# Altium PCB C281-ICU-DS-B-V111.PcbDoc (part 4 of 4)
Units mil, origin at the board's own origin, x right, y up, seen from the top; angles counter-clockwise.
Board outline 9370.03 x 5995.03 mil, 2 copper layers (Top Layer, Bottom Layer); 468 components, 321 nets, 1241 pads, 808 vias.
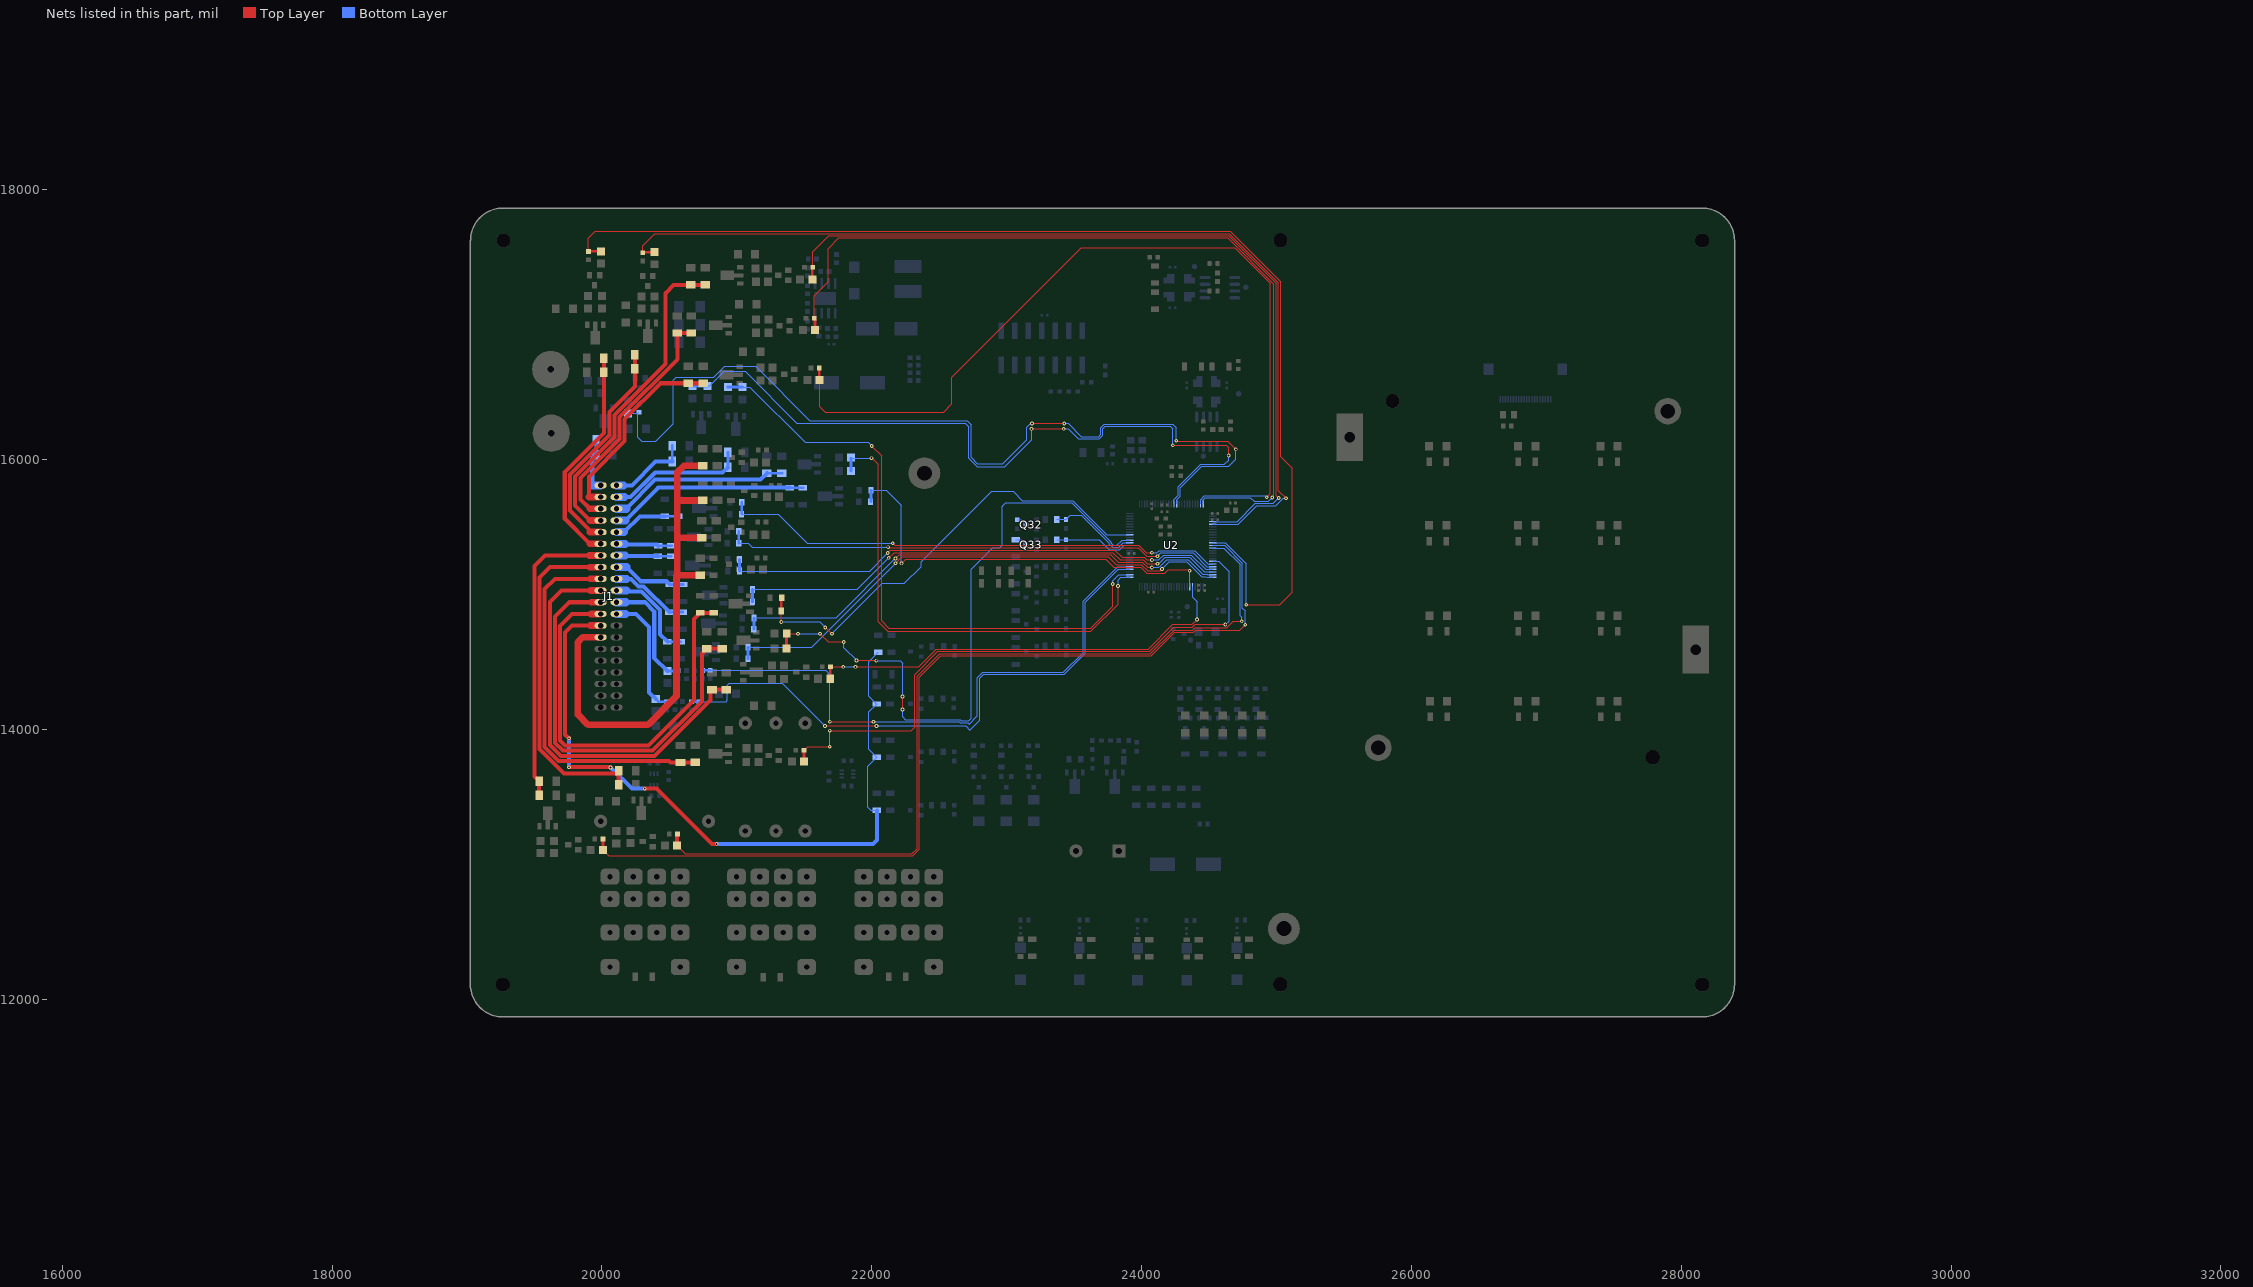
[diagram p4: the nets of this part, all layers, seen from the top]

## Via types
v1: diameter 27.56, hole 13.78, Top Layer to Bottom Layer, tented both sides, 808 vias

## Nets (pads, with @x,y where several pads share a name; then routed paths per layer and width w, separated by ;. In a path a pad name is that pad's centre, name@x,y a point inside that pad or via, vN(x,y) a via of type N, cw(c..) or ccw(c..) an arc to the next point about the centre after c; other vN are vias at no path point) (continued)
按键5: Q33.C R193.2 | length 90.8
  Bottom Layer w7.87: R193.2@23066,15407 23103.86,15407 Q33.C@23141.26,15369.6
按键5_MCU: R189.1 R194.2 U2.13 | length 584.4
  Bottom Layer w7.87: R189.1@23371.61,15407 R194.2@23440,15407 23686.52,15407 23759.52,15334 23839,15334 23870,15365 U2.13@23912.91,15365
按键6: Q32.C R195.2 | length 78.9
  Bottom Layer w7.87: R195.2@23078,15555 23107.11,15555 Q32.C@23142.32,15519.78
按键6_MCU: R188.1 R190.2 U2.14 | length 670
  Bottom Layer w7.87: R188.1@23372,15557.19 23439.19,15557.19 R190.2@23440,15558 23470.45,15588.45 23552.74,15588.45 23760.66,15380.53 23760.66,15374.88 23785.14,15350.39 23829.39,15350.39 23863.69,15384.68 U2.14@23912.91,15384.68
正控_1: J1.11 R53.2 R57.2 | length 3027.7
  Top Layer w30: 19914.47,15030.53 19699.53,15030.53 19613.62,14944.62 19613.62,13886.5 19694.69,13805.43 20389.43,13805.43 20804,14220 20804,14283.97 R57.2@20815.79,14295.77 ; R57.2@20837.77,14295.77 R53.2@20919.22,14295.77
  Top Layer w50: 19914.47,15030.53 J1.11@19989.89,15030.53
正控_1_MCU: R161.2 R199.2 U2.80 | length 3205.8
  Top Layer w7.87: R199.2@21692.05,14463 R199.2@21694.05,14463 ; R199.2@21694.05,14465 v1(21788,14465) ; v1(21880,14465) 22348.58,14465 22478.09,14594.5 24047.5,14594.5 24231.97,14778.97 24374.03,14778.97 v1(24410.53,14815.47)
  Top Layer w20: R161.2@21692.05,14377 R199.2@21692.05,14463
  Bottom Layer w7.87: v1(21788,14465) v1(21880,14465) ; U2.80@24377.48,15057.91 24377.48,14981.52 24410.53,14948.47 v1(24410.53,14815.47)
正控_2: J1.12 R60.2 R61.2 | length 2777.7
  Top Layer w30: 19913.87,15117.14 19652.14,15117.14 19575.75,15040.75 19575.75,13870.81 19679,13767.56 20495.44,13767.56 20506.8,13756.2 R61.2@20582,13756.2 20689.5,13756.2 R60.2@20690,13756.7
  Top Layer w50: 19913.87,15117.14 J1.12@19989.89,15117.14
正控_2_MCU: R165.2 R200.2 U2.69 | length 4450.1
  Top Layer w7.87: R200.2@21497.69,13847 21523.87,13873.19 v1(21688.19,13873.19) ; v1(21688.19,13992.29) 22294.29,13992.29 22320.24,14018.24 22320.24,14408.24 22490.76,14578.76 24058.76,14578.76 24238.49,14758.49 24375.82,14758.49 24396.33,14779 v1(24620.64,14779)
  Top Layer w20: R165.2@21497.69,13762 R200.2@21497.69,13847
  Bottom Layer w7.87: v1(21688.19,13873.19) v1(21688.19,13992.29) ; U2.69@24527.09,15246.89 24571.03,15246.89 24649,15168.92 24649,14804 24624,14779 v1(24620.64,14779)
正控_3: J1.13 R63.2 R64.2 | length 2526.2
  Top Layer w30: 19911.76,15203.76 19615.76,15203.76 19537.87,15125.87 19537.87,13855.13 19717,13676 20106.08,13676 R64.2@20124.01,13693.93 R63.2@20124.01,13590.5
  Top Layer w50: 19911.76,15203.76 J1.13@19989.89,15203.76
正控_3_MCU: R168.2 R201.2 U2.64 | length 6440.2
  Top Layer w7.87: R168.2@20556,13141 20618.25,13078.75 22297,13078.75 22335.99,13117.74 22335.99,14395.99 22503.01,14563.01 24065.28,14563.01 24240.38,14738.11 24377.71,14738.11 24393.01,14753.41 24631.24,14753.41 24679.83,14802 v1(24742,14802)
  Top Layer w30: R168.2@20556,13141 20556,13222 R201.2@20559,13225
  Bottom Layer w7.87: U2.64@24527.09,15345.32 24609.46,15345.32 24730,15224.78 24730,14843 24742,14831 v1(24742,14802)
正控_4: J1.14 R68.2 R69.2 | length 2233.6
  Top Layer w30: R68.2@19534.04,13514.29 R69.2@19534.04,13617.72 19500,13651.75 19500,15211 19579.37,15290.37 19906.37,15290.37
  Top Layer w50: 19906.37,15290.37 J1.14@19989.89,15290.37
正控_4_MCU: R170.2 R202.2 U2.63 | length 7060.2
  Top Layer w7.87: R170.2@20006,13108 20051,13063 22303.52,13063 22351.74,13111.21 22351.74,14389.47 22509.53,14547.26 24071.8,14547.26 24245.67,14721.13 24383,14721.13 24399.53,14737.66 24728.66,14737.66 v1(24768,14777)
  Top Layer w20: R170.2@20006,13108 20007.31,13109.31 R202.2@20007.31,13189
  Bottom Layer w7.87: U2.63@24527.09,15365 24615,15365 24747,15233 24747,14900 24768,14879 v1(24768,14777)
正控_5: J1.15 R81.2 R84.2 | length 1729.1
  Top Layer w30: 19910.02,15376.98 19724.25,15562.75 19724.25,15909.25 20014.96,16199.96 R81.2@20014.96,16725.39 ; R84.2@20013.95,16649.62 R81.2@20013.95,16753.05
  Top Layer w50: 19910.02,15376.98 J1.15@19989.89,15376.98
正控_5_MCU: R171.2 R203.2 U2.62 | length 8830.6
  Top Layer w7.87: R203.2@19900,17543.31 19900,17642.81 19949.19,17692 24657.42,17692 25029.5,17319.93 25029.5,16022.71 25116,15936.21 25116,15016.69 25025,14925.69 v1(24775.37,14925.69)
  Top Layer w20: R203.2@19900,17543.31 19901.47,17544.78 R171.2@19992,17544.78
  Bottom Layer w7.87: U2.62@24527.09,15384.69 24621.41,15384.69 24775.37,15230.73 v1(24775.37,14925.69)
正控_6: J1.16 R131.2 R132.2 | length 1654.3
  Top Layer w30: 19909.4,15463.6 19909.4,15477.82 19762.13,15625.1 19762.13,15892.25 20055,16185.12 20055,16354.87 20243.24,16543.12 R132.2@20243.24,16673.69 R131.2@20243.24,16777.12
  Top Layer w50: 19909.4,15463.6 J1.16@19989.89,15463.6
正控_6_MCU: R196.2 R204.2 U2.55 | length 7287
  Top Layer w7.87: R204.2@20302,17534 20302,17586.78 20391.47,17676.25 24650.9,17676.25 25013.75,17313.4 25013.75,15771.83 v1(25071,15714.58)
  Top Layer w20: R204.2@20302,17534 20307,17539 R196.2@20389,17539
  Bottom Layer w7.87: U2.55@24527.09,15522.48 24716.48,15522.48 24854.21,15660.21 24995.4,15660.21 25049.77,15714.58 v1(25071,15714.58)
正控_7: J1.17 R41.2 R42.2 | length 2407.7
  Top Layer w30: 19911.79,15550.21 19800,15662 19800,15876.56 20092.87,16169.44 20092.87,16331.68 20470,16708.81 20470,17234 20531.74,17295.74 20762.45,17295.74 R41.2@20765.23,17298.52
  Top Layer w50: 19911.79,15550.21 J1.17@19989.89,15550.21
正控_7_MCU: R158.2 R197.2 U2.54 | length 5997.1
  Top Layer w7.87: R197.2@21562,17427 21562,17541.3 21681.2,17660.5 24644.38,17660.5 24998,17306.88 24998,15735 v1(25016,15717)
  Top Layer w20: R158.2@21559,17336 21559,17424 R197.2@21562,17427
  Bottom Layer w7.87: U2.54@24527.09,15542.17 24708.61,15542.17 24842.4,15675.96 24974.96,15675.96 v1(25016,15717)
正控_8: J1.18 R222.2 R223.2 | length 1812.2
  Top Layer w30: 19909.83,15636.83 19841,15705.66 19841,15864 20130.75,16153.75 20130.75,16316 20559.57,16744.82 R223.2@20559.57,16939.36 R222.2@20663,16939.36
  Top Layer w50: 19909.83,15636.83 J1.18@19989.89,15636.83
正控_8_MCU: R226.2 R231.2 U2.50 | length 6285.9
  Top Layer w7.87: R231.2@21573,17049 21573,17215 21677,17319 21677,17565.63 21756.13,17644.76 24637.85,17644.76 24980,17302.61 24980,15732 v1(24968,15720)
  Top Layer w20: R231.2@21573,17049 21579,17043 R226.2@21579,16962.35
  Bottom Layer w7.87: U2.50@24456.22,15672.09 24456.22,15702.68 24472.36,15718.82 24806.18,15718.82 24833.29,15691.71 24939.71,15691.71 v1(24968,15720)
正控_9: J1.19 R218.2 R219.2 | length 1572.1
  Top Layer w30: 19904.56,15723.44 19904.56,15874 20168.62,16138.06 20168.62,16300.31 20435.32,16567.01 R218.2@20749.5,16567.01 20749,16566.51 R219.2@20640.5,16566.51
  Top Layer w50: 19904.56,15723.44 J1.19@19989.89,15723.44
正控_9_MCU: R224.2 R227.2 U2.49 | length 6512.1
  Top Layer w7.87: R224.2@21613,16580 21613,16394.73 21656.05,16351.68 22531.64,16351.68 22594,16414.04 22594,16613 23551,17570 24690.34,17570 24952.51,17307.83 24952.51,15746.74 v1(24927.77,15722)
  Top Layer w20: R227.2@21611,16681 21611,16582 R224.2@21613,16580
  Bottom Layer w7.87: U2.49@24436.54,15672.09 24436.54,15705.26 24465.84,15734.57 24915.2,15734.57 v1(24927.77,15722)
正控_10: J1.20 R220.2 R221.2 | length 411.8
  Bottom Layer w16: R221.2@19954.02,16037.35 R221.2@19956.01,16039.34
  Bottom Layer w20: R221.2@19956.01,16039.34 R220.2@19956.01,16148.35
  Bottom Layer w30: 19927.97,15810.06 19927.97,16011.3 R221.2@19954.02,16037.35
  Bottom Layer w60: 19927.97,15810.06 J1.20@19989.89,15810.06
正控_10_MCU: R225.2 R228.2 U2.40 | length 6688.9
  Top Layer w7.87: v1(23187.63,16269) v1(23427,16269) ; v1(24257.14,16141) 24262.33,16135.82 24639.82,16135.82 v1(24698.64,16077)
  Bottom Layer w7.87: R225.2@20194,16343.85 R228.2@20266.12,16343.85 ; R228.2@20274,16351.73 R228.2@20266.12,16343.85 ; v1(23187.63,16269) 23178,16269 23149,16240 23149,16148 22972,15971 22782,15971 22736,16017 22736,16260 22706,16290 21542,16290 21140.07,16691.93 20908.93,16691.93 20829,16612 20550.71,16612 20529.63,16590.92 20529.63,16267.63 20400.32,16138.32 20294.31,16138.32 20264.23,16168.4 20264.23,16341.96 R228.2@20266.12,16343.85 ; v1(23427,16269) 23457,16269 23554.37,16171.63 23681.31,16171.63 23697,16187.33 23697,16235.61 23724.39,16263 24232,16263 24257.14,16237.86 v1(24257.14,16141) ; U2.40@24259.37,15672.09 24259.37,15702.37 24286.93,15729.93 24286.93,15793.47 24444.46,15951 24646.7,15951 24698.64,16002.94 v1(24698.64,16077)
水温: J1.7 R245.1 R247.1 R257.1 R263.1 | length 3986.8
  Top Layer w50: J1.7@19989.89,14684.07 19857.07,14684.07 19821,14648 19821,14112 19898,14035 20340,14035 20553,14248 20553,15140 20557.62,15144.62 ; R257.1@20729.26,15144.62 20557.62,15144.62 ; R263.1@20739.79,15421.52 20561.13,15421.52 20557.62,15418 ; R247.1@20745.5,15698.59 20563.21,15698.59 20557.62,15693 ; R245.1@20746.99,15955.62 20608.02,15955.62 20557.62,15905.21 20557.62,15693 ; 20557.62,15144.62 20557.62,15418 ; 20557.62,15418 20557.62,15693
燃油: J1.8 R47.1 R49.1 R52.1 R54.1 | length 5403.8
  Top Layer w30: v1(19755.35,13721) 20062.22,13721 v1(20063.97,13719.24) ; v1(19757,13936) 19755,13934 19727.24,13961.76 19727.24,14720.24 19777.68,14770.68 19912.32,14770.68 ; v1(20317,13562) 20406,13562 20815,13153 v1(20850,13153)
  Top Layer w50: 19912.32,14770.68 J1.8@19989.89,14770.68
  Bottom Layer w7.87: R54.1@22037.4,13401.57 21992.13,13401.57 21969,13424.7 21969,13726.87 R47.1@22037.4,13795.28 21979,13853.68 21979,14130.57 R49.1@22037.4,14188.98 21979,14247.38 21979,14504.59 R52.1@22047.24,14572.83
  Bottom Layer w30: v1(19755.35,13721) 19755.35,13934.35 v1(19757,13936) ; v1(20063.97,13719.24) 20221.22,13562 v1(20317,13562) ; v1(20850,13153) 22008,13153 22037.4,13182.4 R54.1@22037.4,13401.57
负控_1: J1.31 R26.2 R27.2 | length 738
  Bottom Layer w20: R27.2@20485.25,14651.4 R26.2@20583.67,14651.4
  Bottom Layer w30: 20182,15030.52 20188.76,15023.76 20292.64,15023.76 20430.14,14886.26 20430.14,14706.51 R27.2@20485.25,14651.4
  Bottom Layer w60: J1.31@20108,15030.52 20182,15030.52
负控_1_MCU: R103.2 R112.2 U2.75 | length 3931.7
  Top Layer w7.87: v1(22176,15233) 22222.47,15279.47 23754.34,15279.47 23812.81,15221 23999,15221 24044,15176 24137,15176 v1(24151,15190)
  Bottom Layer w7.87: R103.2@21082.62,14610.11 21082.9,14609.83 21555.83,14609.83 22179,15233 v1(22176,15233) ; v1(24151,15190) 24205,15244 24334.27,15244 24444.06,15134.21 24479.47,15134.21 24484.9,15128.78 U2.75@24527.09,15128.78
  Bottom Layer w20: R103.2@21082.62,14610.11 21082.62,14525.65 R112.2@21083,14525.27
负控_2: J1.32 R28.2 R29.2 | length 592.6
  Bottom Layer w20: R28.2@20500.1,14870.8 R29.2@20598.53,14870.8
  Bottom Layer w30: 20182.86,15117.14 20214.05,15117.14 20269.55,15061.64 20308.32,15061.64 20499.16,14870.8 R28.2@20500.1,14870.8
  Bottom Layer w60: J1.32@20108,15117.14 20182.86,15117.14
负控_2_MCU: R106.2 R113.2 U2.74 | length 3787.9
  Top Layer w7.87: v1(22175,15268.86) 22202.14,15296 23770.92,15296 23826.92,15240 24006.25,15240 24044.25,15202 v1(24076,15202)
  Bottom Layer w7.87: R106.2@21126.62,14827.73 21127.62,14828.73 21734.88,14828.73 v1(22175,15268.86) ; v1(24076,15202) 24126.81,15202 24140.4,15215.59 24140.59,15215.59 24185,15260 24346.38,15260 24454.29,15152.09 24486.87,15152.09 24490.49,15148.46 U2.74@24527.09,15148.46
  Bottom Layer w20: R113.2@21124.31,14744.4 21126.62,14746.72 R106.2@21126.62,14827.73
负控_3: J1.33 R30.2 R31.2 | length 547.3
  Bottom Layer w20: R31.2@20503.82,15075.65 R30.2@20602.25,15075.65
  Bottom Layer w30: 20181,15203.76 20285.24,15099.51 20479.96,15099.51 R31.2@20503.82,15075.65
  Bottom Layer w60: J1.33@20108,15203.76 20181,15203.76
负控_3_MCU: R107.2 R114.2 U2.73 | length 3714.3
  Top Layer w7.87: v1(22125.96,15273) 22164.96,15312 23787.71,15312 23840.71,15259 24012.09,15259 24042.09,15229 v1(24117,15229)
  Bottom Layer w7.87: R107.2@21115.62,15038.28 21115.94,15038.59 21891.56,15038.59 v1(22125.96,15273) ; v1(24117,15229) 24128,15229 24174.91,15275.91 24358.07,15275.91 24464.02,15169.96 24494.27,15169.96 24496.08,15168.15 U2.73@24527.09,15168.15
  Bottom Layer w20: R107.2@21115.62,15038.28 21115.62,14948.22 R114.2@21116.31,14947.53
负控_4: J1.34 R32.2 R74.2 | length 407.8
  Bottom Layer w16: 20170.63,15290.37 20176.01,15284.99
  Bottom Layer w20: R32.2@20415.1,15284.99 R74.2@20513.53,15284.99
  Bottom Layer w30: 20176.01,15284.99 R32.2@20415.1,15284.99
  Bottom Layer w60: J1.34@20108,15290.37 20170.63,15290.37
负控_4_MCU: R108.2 R115.2 U2.72 | length 3745.2
  Top Layer w7.87: v1(22118,15309) 22138,15329 23802.68,15329 23855.68,15276 24018.75,15276 24037.75,15257 v1(24076,15257)
  Bottom Layer w7.87: R115.2@21019.13,15175.54 21020.13,15174.54 21983.54,15174.54 v1(22118,15309) ; v1(24076,15257) 24128,15257 24164,15293 24368.81,15293 24473.98,15187.83 U2.72@24527.09,15187.83
  Bottom Layer w20: R115.2@21019.13,15175.54 R108.2@21019.13,15260.12
负控_5: J1.35 R88.2 R90.2 | length 413.1
  Bottom Layer w16: 20170.93,15376.98 20177.46,15370.46
  Bottom Layer w20: R88.2@20416.72,15362.66 R90.2@20515.15,15362.66
  Bottom Layer w30: 20177.46,15370.46 20408.93,15370.46 R88.2@20416.72,15362.66
  Bottom Layer w60: J1.35@20108,15376.98 20170.93,15376.98
负控_5_MCU: R109.2 R116.2 U2.71 | length 3694
  Top Layer w7.87: v1(22121,15352) 22127,15346 23975.52,15346 24026.27,15295.25 24026.48,15295.25 24036.73,15285 v1(24117,15285)
  Bottom Layer w7.87: R116.2@21014.13,15382 21085.04,15382 21115.04,15352 v1(22121,15352) ; v1(24117,15285) 24142.2,15310.2 24381.8,15310.2 24484.48,15207.52 U2.71@24527.09,15207.52
  Bottom Layer w20: R116.2@21014.13,15382 R109.2@21014.13,15469.94
负控_6: J1.36 R92.2 R94.2 | length 504.8
  Bottom Layer w20: R92.2@20465.9,15580.51 R94.2@20564.32,15580.51
  Bottom Layer w30: 20164.6,15463.6 20281.51,15580.51 R92.2@20465.9,15580.51
  Bottom Layer w60: J1.36@20108,15463.6 20164.6,15463.6
负控_6_MCU: R110.2 R117.2 U2.70 | length 3746.3
  Top Layer w7.87: v1(22155,15381) 22171,15365 23978.79,15365 24032.79,15311 v1(24076,15311)
  Bottom Layer w7.87: R117.2@21035.98,15598.67 R117.2@21034.31,15597 21305.68,15597 21521.68,15381 v1(22155,15381) ; v1(24076,15311) 24114,15311 24128.95,15325.95 24393.64,15325.95 24492.39,15227.2 U2.70@24527.09,15227.2
  Bottom Layer w20: R117.2@21035.98,15598.67 R110.2@21035.98,15684.31
负控_7: J1.37 R96.2 R101.2 | length 1482.7
  Bottom Layer w20: R101.2@21391.43,15793.56 R96.2@21489.85,15793.56
  Bottom Layer w30: 20173.92,15550.21 20417.26,15793.56 R101.2@21391.43,15793.56
  Bottom Layer w60: J1.37@20108,15550.21 20173.92,15550.21
负控_7_MCU: R111.2 R118.2 U2.81 | length 3122.3
  Top Layer w7.87: v1(22220,15232) 22251.61,15263.61 23734.39,15263.61 23795,15203 23994.73,15203 24037.48,15160.25 24037.65,15160.25 24038.91,15159 24172,15159 24198.17,15185.17 24347.83,15185.17 v1(24356,15177) v1@24361.02,15177
  Bottom Layer w7.87: R111.2@21993.65,15774.2 22108.55,15774.2 22220,15662.75 v1(22220,15232) ; v1(24356,15177) 24356,15170.54 24357.8,15168.75 U2.81@24357.8,15057.91
  Bottom Layer w10: R118.2@21990.36,15688 R118.2@21993.65,15691.29
  Bottom Layer w20: R118.2@21993.65,15691.29 R111.2@21993.65,15774.2
负控_8: J1.38 R7.2 R8.2 | length 1337
  Bottom Layer w16: R7.2@21222.02,15899.92 R7.2@21223.02,15898.92
  Bottom Layer w20: R7.2@21223.02,15898.92 R8.2@21334.02,15898.92
  Bottom Layer w30: 20182.14,15636.83 20182.14,15639.58 20394.56,15852 21174.1,15852 R7.2@21222.02,15899.92
  Bottom Layer w60: J1.38@20108,15636.83 20182.14,15636.83
负控_8_MCU: R35.2 R38.2 U2.1 | length 3646.7
  Top Layer w7.87: v1(21998,16012) 22003,16012 22049,15966 22049,14797.47 22117.47,14729 23624,14729 23825,14930 v1(23825,15065)
  Bottom Layer w7.87: R35.2@21846.39,16011.86 21846.52,16012 v1(21998,16012) ; v1(23825,15065) 23825,15106.78 23847,15128.78 U2.1@23912.91,15128.78
  Bottom Layer w20: R38.2@21846.39,15916.86 R35.2@21846.39,16011.86
负控_9: J1.39 R13.2 R14.2 | length 1026.4
  Bottom Layer w20: R14.2@20933.51,15944.46 R13.2@20933.51,16055.18
  Bottom Layer w30: 20167.44,15723.44 20212.44,15723.44 20395,15906 20895.05,15906 R14.2@20932.51,15943.46
  Bottom Layer w60: J1.39@20108,15723.44 20167.44,15723.44
负控_9_MCU: R36.2 R39.2 U2.2 | length 4711.7
  Top Layer w7.87: v1(22000,16101.93) 22072,16029.93 22072,14807 22127,14752 23624,14752 23786,14914 v1(23786,15079)
  Bottom Layer w7.87: R39.2@21041.04,16538.99 21097.01,16538.99 21508,16128 21973.93,16128 v1(22000,16101.93) ; v1(23786,15079) 23786,15103.6 23830.86,15148.46 U2.2@23912.91,15148.46
  Bottom Layer w20: R36.2@20933.04,16538.99 R39.2@21041.04,16538.99
负控_10: J1.40 R16.2 R17.2 | length 588.3
  Bottom Layer w20: R17.2@20522,16004.01 R16.2@20522,16105.01
  Bottom Layer w30: 20159.95,15810.05 20221.54,15810.05 20398.5,15987.01 R17.2@20522,15987.01
  Bottom Layer w60: J1.40@20108,15810.05 20159.95,15810.05
负控_10_MCU: R37.2 R40.2 U2.39 | length 5534.5
  Top Layer w7.87: v1(23184.54,16229.09) v1(23423,16229.09) ; v1(24231.81,16107.48) 24625.48,16107.48 24626,16108 24645,16089 v1(24645,16031.73)
  Bottom Layer w7.87: R40.2@20779.63,16545.09 R40.2@20781.63,16547.09 20798.74,16547.09 20906.66,16655 21060.35,16655 21445.35,16270 22694,16270 22720.25,16243.75 22720.25,16010.48 22781.73,15949 22985,15949 23184.54,16148.54 v1(23184.54,16229.09) ; v1(23423,16229.09) 23456.26,16229.09 23457.18,16228.18 23529.47,16155.89 23687.83,16155.89 23712.75,16180.8 23712.75,16229.09 23730.91,16247.25 24213.36,16247.25 24231.55,16229.06 24231.55,16107.74 v1(24231.81,16107.48) ; U2.39@24239.69,15672.09 24239.69,15704.96 24271.18,15736.45 24271.18,15799.99 24437.94,15966.75 24614.29,15966.75 24645,15997.46 v1(24645,16031.73)
  Bottom Layer w20: R37.2@20669.97,16545.09 R40.2@20779.63,16545.09
车速_IOC: J1.29 R240.1 R241.2 | length 924
  Bottom Layer w20: R240.1@20399,14226.04 20418.72,14206.32 R241.2@20479,14206.32
  Bottom Layer w30: 20173.7,14857.3 20251.52,14857.3 20349.62,14759.2 20349.62,14275.41 R240.1@20399,14226.04
  Bottom Layer w60: J1.29@20108,14857.3 20173.7,14857.3
车速_MCU_IOC: C10.1 R242.1 U2.4 | length 4418.1
  Top Layer w7.87: v1(21653,14026) 21654,14027 v1(22035,14027)
  Bottom Layer w7.87: C10.1@20719,14206.32 20920.31,14206.32 20929.56,14215.56 20929.56,14328.25 20944.31,14343 21338.16,14343 21653,14028.16 v1(21653,14026) ; v1(22035,14027) 22695.16,14027 22727.08,13995.08 22802,14070 22802,14382 22829.25,14409.25 23426.99,14409.25 23582,14564.26 23582,14944.14 23825.69,15187.83 U2.4@23912.91,15187.83
  Bottom Layer w20: R242.1@20663,14206.32 C10.1@20719,14206.32
车速_PWM: J1.9 R121.2 R122.2 | length 3100.2
  Top Layer w30: 19919.3,14857.3 19777.3,14857.3 19689.37,14769.37 19689.37,13917.88 19725.37,13881.87 20344.32,13881.87 20682,14219.56 20682,14820.14 R121.2@20726.86,14865 R122.2@20827.2,14865
  Top Layer w50: 19919.3,14857.3 J1.9@19989.89,14857.3
车速_PWM_MCU: R123.2 R124.2 U2.17 | length 3393.3
  Top Layer w7.87: v1(21329.8,14797.67) R123.2@21329.8,14879.23 ; v1(21655,14757) 21702,14710 v1(21705,14710)
  Top Layer w20: R123.2@21329.8,14879.23 21329.8,14976.11 R124.2@21331.8,14978.11
  Bottom Layer w7.87: v1(21329.8,14797.67) 21614.33,14797.67 v1(21655,14757) ; v1(21705,14710) 22078,15083 22241.74,15083 22366,15207.26 22366,15243 22890,15767 23047,15767 23116.25,15697.75 23487.98,15697.75 23741.99,15443.74 U2.17@23912.91,15443.74
转速_IOC: J1.30 R244.1 R252.2 | length 871.7
  Bottom Layer w20: R244.1@20484.5,14434.61 20562.69,14434.61 R252.2@20566,14437.92
  Bottom Layer w30: 20176.03,14943.91 20318.93,14943.91 20387.5,14875.34 20387.5,14531.61 R244.1@20484.5,14434.61
  Bottom Layer w60: J1.30@20108,14943.91 20176.03,14943.91
转速_MCU_IOC: C16.1 R253.1 U2.5 | length 4409.8
  Top Layer w7.87: v1(21689,14058) v1(22012,14058)
  Bottom Layer w7.87: C16.1@20803,14439.76 21657.24,14439.76 21689,14408 v1(21689,14058) ; v1(22012,14058) 22648.54,14058 22656.88,14049.66 22712.68,14049.66 22721,14041.34 22783,14103.34 22783,14386 22822,14425 23420.46,14425 23566.25,14570.79 23566.25,14950.67 23823.11,15207.52 U2.5@23912.91,15207.52
  Bottom Layer w20: R253.1@20744.64,14438.92 20802.16,14438.92 C16.1@20803,14439.76
转速_PWM: J1.10 R236.2 R237.2 | length 3101.5
  Top Layer w30: 19921.91,14943.91 19758.91,14943.91 19651.5,14836.5 19651.5,13902.19 19709.69,13844 20374.44,13844 20740,14209.56 20740,14562.01 R237.2@20777.43,14599.44 20890.89,14599.44 R236.2@20891.89,14600.44
  Top Layer w50: 19921.91,14943.91 J1.10@19989.89,14943.91
转速_PWM_MCU: R238.2 R239.2 U2.15 | length 4817.5
  Top Layer w7.87: R239.2@21369.78,14711.26 21371.04,14710 v1(21453,14710) ; v1(21616,14710) 21676.39,14649.61 v1(21792,14649.61) ; v1(21887,14512.19) 22032.65,14512.19 v1(22034,14510.84) ; v1(22228,14149) v1(22228,14246)
  Top Layer w20: R238.2@21367.78,14601.26 21367.78,14709.26 R239.2@21369.78,14711.26
  Bottom Layer w7.87: v1(21453,14710) v1(21616,14710) ; v1(21792,14649.61) 21792,14607.19 v1(21887,14512.19) ; v1(22034,14510.84) 22209.75,14510.84 22228,14492.59 v1(22228,14246) ; v1(22228,14149) 22228,14093.51 22247.76,14073.75 22655.06,14073.75 22663.4,14065.41 22718.41,14065.41 22736.59,14083.59 22736.59,15074.28 22736.47,15074.4 22736.47,15095.6 22736.59,15095.72 22736.59,15167.28 22736.47,15167.4 22736.47,15188.6 22895.87,15348 22948.81,15348 22968.59,15367.78 22968.59,15653.41 22967,15655 22994,15682 23481.46,15682 23776.41,15387.05 23776.41,15381.4 23791.4,15366.41 23816.73,15366.41 23854.69,15404.37 U2.15@23912.91,15404.37
pads on no net: DL1.1 DL1.2 DL1.3 DL1.4 DL2.1 DL2.2 DL2.3 DL2.4 DL3.1 DL3.2 DL3.3 DL3.4 H1.1 H2.1 H3.1 H4.1 H7.1 H8.1 J2.10 U5.5 U8.5 Y1.2 Y1.4

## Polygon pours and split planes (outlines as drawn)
GND on Top Layer "bottom-Layer-gnd" (solid, remove dead copper, pour order 18): 18753,18013 18755,18015 28886,18015 28886,11471 28875,11460 28842,11427 18791,11427
GND on Bottom Layer "bottom-Layer-gnd" (solid, remove dead copper, pour order 20): 18780,18299 28602,18299 28645,18256 28645,11580 18693,11580

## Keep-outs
Keep-Out Layer:
  lines w1.97: 26124,16812.37 ccw(c26163.37,16812.37) 26163.37,16773 27544.63,16773 ccw(c27544.63,16812.37) 27584,16812.37 27584,16967.63 ccw(c27544.63,16967.63) 27544.63,17007 26163.37,17007 ccw(c26163.37,16967.63) 26124,16967.63 26124,16812.37
  lines w10: 19030,12300 19030,16835 19030,17625.73 ; 19030,12310 19030,12110 ccw(c19265,12110) 19265,11875 27545,11875 27890,11875 28153.78,11875 ccw(c28153.89,12111.11) 28390,12111 28390,17625.78 ccw(c28155.78,17625.78) 28155.78,17860 27810,17860 27355,17860 24800,17860 19805,17860 19265,17860 ccw(c19265,17625.73) 19030.73,17625.73

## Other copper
Top Layer:
  region net GND: 24584,13153.96 24514,13153.96 24514,13086.96 24584,13086.96
  region net GND: 24495.83,13156.65 24425.83,13156.65 24425.83,13089.65 24495.83,13089.65
  region net GND: 24587,12909.65 24517,12909.65 24517,12842.65 24587,12842.65
  region net GND: 24489,12909.65 24419,12909.65 24419,12842.65 24489,12842.65
  region net GND: 24831,12759 24761,12759 24761,12692 24831,12692
  region net SYS_VCC_5: 21864.17,13554.13 21831,13554.13 21831,13464.57 21864.17,13464.57
  region net SYS_VCC_5: 24754.61,16242 24716,16242 24716,16165 24754.61,16165
  region net VCC12V_SYS: 23229.36,13253 23168,13253 23168,13157 23229.36,13157
  region net SYS_VCC_5: 23034,15742 22926,15742 22926,15704.96 23034,15704.96
  region net VCC12V_SYS: 20548,17464.78 20491,17464.78 20491,17371 20548,17371
  region net VCC12V_SYS: 21046.66,17182 20838.49,17182 20838.49,17121 21046.66,17121
  region net VCC12V_SYS: 21076.44,16832.07 20885,16832.07 20885,16770 21076.44,16770
  region net VCC12V_SYS: 20206.43,17405 20144.71,17405 20144.71,17218 20206.43,17218
  region net VCC12V_SYS: 19687,17151 19511,17151 19511,17090.67 19687,17090.67
  region net VCC12V_SYS: 19799,13638.01 19738,13638.01 19738,13467 19799,13467
  region net VCC12V_SYS: 19927,13966 19826,13966 19826,13907 19927,13907
  region net VCC12V_SYS: 20168,13965 20077,13965 20077,13908 20168,13908
  region: 24324,16434 24320,16434 24320,16433 24324,16433
  region net SYS_VCC_5: 24320.25,16397.84 24283.86,16397.84 24283.86,16331 24320.25,16331
  region net GND: 21325,16144.01 21254.3,16144.01 21254.3,16109 21325,16109
  region net GND: 20838.99,16499 20838.99,16428.3 20874,16428.3 20874,16499
  rectangle net GND: 21563,15831.99 21633.7,15867
  rectangle net GND: 21741,15586.99 21811.7,15622
  rectangle net GND: 21017,15301.99 21087.7,15337
  rectangle net GND: 20972,15093.99 21042.7,15129
  rectangle net GND: 21552,14897.99 21622.7,14933
  region net GND: 21249.5,14811.39 21178.8,14811.39 21178.8,14776.38 21249.5,14776.38
  region net GND: 21594,14563.29 21523.3,14563.29 21523.3,14528.28 21594,14528.28
  region net GND: 21528,14337.01 21457.3,14337.01 21457.3,14302 21528,14302
  region net GND: 20386.99,14383 20386.99,14312.3 20422,14312.3 20422,14383
  region net GND: 20783,14112.51 20832.99,14162.5 20808.23,14187.26 20758.24,14137.27
  region net GND: 21828.99,13971 21828.99,13900.3 21864,13900.3 21864,13971
  rectangle net GND: 20583,13664.99 20653.7,13700
  rectangle net GND: 20638,13172.99 20708.7,13208
  region net GND: 19780.14,13218 19780.14,13288.7 19745.13,13288.7 19745.13,13218
  region net GND: 21747.01,13514 21747.01,13584.7 21712,13584.7 21712,13514
  region net GND: 22523,13382.01 22452.3,13382.01 22452.3,13347 22523,13347
  region net GND: 22520,13769.04 22454,13769.04 22454,13734.02 22520,13734.02
  region net GND: 22522,14163.01 22451.3,14163.01 22451.3,14128 22522,14128
  region net GND: 22532,14403.01 22461.3,14403.01 22461.3,14368 22532,14368
  region net GND: 23220.99,13797 23220.99,13726.3 23256,13726.3 23256,13797
  region net GND: 23036.47,13797.82 23036.47,13727.12 23071.48,13727.12 23071.48,13797.82
  region net GND: 22829.57,13795.78 22829.57,13725.08 22864.58,13725.08 22864.58,13795.78
  rectangle net GND: 23300,14912.63 23370.7,14947.64
  rectangle net GND: 23296,15112.99 23366.7,15148
  region net GND: 23526.01,14773 23526.01,14843.7 23491,14843.7 23491,14773
  region net GND: 23361,14503.01 23290.3,14503.01 23290.3,14468 23361,14468
  region net GND: 23592,15248.01 23521.3,15248.01 23521.3,15213 23592,15213
  region net GND: 23917.58,14041.01 23846.88,14041.01 23846.88,14006 23917.58,14006
  region net GND: 23778.58,13874.43 23707.88,13874.43 23707.88,13839.42 23778.58,13839.42
  region net GND: 24828,12679.42 24757.3,12679.42 24757.3,12644.41 24828,12644.41
  rectangle net GND: 24446,12514 24510.3,12544.97
  region net GND: 24051.99,12704 24051.99,12633.3 24087,12633.3 24087,12704
  region net GND: 23626.05,12711 23626.05,12640.3 23661.06,12640.3 23661.06,12711
  region net GND: 23210.35,12641.3 23210.35,12570.61 23245.36,12570.61 23245.36,12641.3
  rectangle net GND: 22904,12109.99 22974.7,12145
  rectangle net GND: 23737.34,16190.74 23808.04,16225.75
  rectangle net GND: 24209,15594.99 24279.7,15630
  region net GND: 22519,13711.01 22456,13711.01 22456,13676 22519,13676
  region net GND: 24946.59,14159.43 24946.59,14222.43 24911.57,14222.43 24911.57,14159.43
  region net GND: 22526,13270 22458,13270 22458,13204 22526,13204
  region net GND: 22224.9,16627.56 22156.9,16627.56 22156.9,16561.56 22224.9,16561.56
  region net GND: 22223.61,16701.56 22155.61,16701.56 22155.61,16635.56 22223.61,16635.56
  region net GND: 22222.72,16776.44 22154.72,16776.44 22154.72,16710.44 22222.72,16710.44
  region net GND: 22127.72,16704.56 22059.72,16704.56 22059.72,16638.56 22127.72,16638.56
  region net GND: 22127.72,16776.56 22059.72,16776.56 22059.72,16710.56 22127.72,16710.56
  region net GND: 21857.72,16992.61 21789.72,16992.61 21789.72,16926.61 21857.72,16926.61
  region net GND: 21857.84,16891.56 21789.84,16891.56 21789.84,16825.56 21857.84,16825.56
  region net GND: 21954.72,16890.56 21886.72,16890.56 21886.72,16824.56 21954.72,16824.56
  region net GND: 22041.72,16891.78 21973.72,16891.78 21973.72,16825.78 22041.72,16825.78
  region net GND: 22040.72,16790.87 21972.72,16790.87 21972.72,16724.87 22040.72,16724.87
  region net GND: 21951.72,16792.56 21883.72,16792.56 21883.72,16726.56 21951.72,16726.56
  region net GND: 22040.72,16714.99 21972.72,16714.99 21972.72,16648.99 22040.72,16648.99
  region net GND: 21951.72,16714.56 21883.72,16714.56 21883.72,16648.56 21951.72,16648.56
  region net GND: 22002.72,17110.56 21934.72,17110.56 21934.72,17044.56 22002.72,17044.56
  region net GND: 21448.17,16828.98 21377.48,16828.98 21377.48,16793.97 21448.17,16793.97
  region net GND: 21309.95,17169.84 21239.26,17169.84 21239.26,17134.83 21309.95,17134.83
  region net GND: 21373.17,17526.84 21302.48,17526.84 21302.48,17491.83 21373.17,17491.83
  region net GND: 20192.17,17604.84 20121.48,17604.84 20121.48,17569.83 20192.17,17569.83
  region net GND: 19799.17,17607.84 19728.48,17607.84 19728.48,17572.83 19799.17,17572.83
  region net GND: 20360.85,16326 20360.85,16396.7 20325.83,16396.7 20325.83,16326
  rectangle net GND: 22954.97,17073.27 23025.66,17108.28
  rectangle net GND: 23564.83,16491.83 23635.52,16526.84
  region net GND: 24069.17,14949.48 23998.48,14949.48 23998.48,14914.47 24069.17,14914.47
  rectangle net GND: 24275.39,14605.35 24346.08,14640.36
  region net GND: 23453.17,15761.84 23382.48,15761.84 23382.48,15726.83 23453.17,15726.83
  region net GND: 23554,15561.41 23483.3,15561.41 23483.3,15526.4 23554,15526.4
  region net GND: 23344,15655.48 23273.3,15655.48 23273.3,15620.47 23344,15620.47
  region net SYS_VCC_5: 24547.35,17517 24547.35,17481.49 24626.94,17481.49 24626.94,17517
  region net NetQ39_C: 20029,17316 19867,17316 19867,17183.18 20029,17183.18
  region net NetQ40_C: 20419,17312 20260,17312 20260,17181 20419,17181
  region net NetQ34_C: 21331,17447 21201,17447 21201,17291 21331,17291
  region net NetQ50_C: 21340,17070.25 21204,17070.25 21204,16912.02 21340,16912.02
  region net NetQ48_C: 21375,16712 21236,16712 21236,16553 21375,16553
  region net NetQ35_C: 21467,14508 21319,14508 21319,14347 21467,14347
  region net NetQ36_C: 21261,13891 21131,13891 21131,13731.93 21261,13731.93
  region net VCC5V_SYS: 24503,14970.75 24462,14970.75 24462,14860.84 24503,14860.84
  region net GND: 21380.7,15456 21309.47,15456 21309.47,15422.46 21380.7,15422.46
  region net GND: 21109.99,16450 21109.99,16379.3 21145,16379.3 21145,16450
  region net GND: 21168,14280.01 21097.3,14280.01 21097.3,14245 21168,14245
  region net GND: 23971.14,17515.79 23900.44,17515.79 23900.44,17480.78 23971.14,17480.78
  region net GND: 23972,17454.01 23901.3,17454.01 23901.3,17419 23972,17419
  region net GND: 28211.5,14795.23 28229,14777.73 28229,14402 28217,14390 28004.83,14390 27989,14405.83 27989,14783.48 28000.75,14795.23
  region net GND: 25645.5,16369.23 25663,16351.73 25663,15976 25651,15964 25438.83,15964 25423,15979.83 25423,16357.48 25434.75,16369.23
  region net POWER: 20073,12582.68 22520.32,12582.68 22552,12551 22552,12452 22518,12418 19763,12418 19737,12444 19737,12559 19760.68,12582.68
  region net SYS_VCC_5: 24626,15091 24551,15091 24551,15005 24626,15005
  region net SYS_VCC_5: 22917,16490 22792,16490 22792,16385 22917,16385
  region net GND: 25782.91,16435.45 ccw(c25860.1,16435.45) 25860.1,16358.26 ccw(c25860.1,16435.45) 25937.29,16435.45 ccw(c25860.1,16435.45) 25860.1,16512.64 ccw(c25860.1,16435.45)
  region net GND: 24871.71,12524.06 ccw(c25054,12524.06) 25054,12341.77 ccw(c25054,12524.06) 25236.29,12524.06 ccw(c25054,12524.06) 25054,12706.35 ccw(c25054,12524.06)
  region net GND: 27606.28,13792.78 ccw(c27788.57,13792.78) 27788.57,13610.48 ccw(c27788.57,13792.78) 27970.86,13792.78 ccw(c27788.57,13792.78) 27788.57,13975.07 ccw(c27788.57,13792.78)
  region net GND: 25570.6,13863.64 ccw(c25752.89,13863.64) 25752.89,13681.35 ccw(c25752.89,13863.64) 25935.18,13863.64 ccw(c25752.89,13863.64) 25752.89,14045.93 ccw(c25752.89,13863.64)
  region net GND: 27716.26,16359.7 ccw(c27898.55,16359.7) 27898.55,16177.41 ccw(c27898.55,16359.7) 28080.85,16359.7 ccw(c27898.55,16359.7) 27898.55,16542 ccw(c27898.55,16359.7)
  region net GND: 22206.71,15899.06 ccw(c22389,15899.06) 22389,15716.77 ccw(c22389,15899.06) 22571.29,15899.06 ccw(c22389,15899.06) 22389,16081.35 ccw(c22389,15899.06)
  region net GND: 19440.71,16196.06 ccw(c19623,16196.06) 19623,16013.77 ccw(c19623,16196.06) 19805.29,16196.06 ccw(c19623,16196.06) 19623,16378.35 ccw(c19623,16196.06)
Bottom Layer:
  region net GND: 24584,13153.96 24514,13153.96 24514,13086.96 24584,13086.96
  region net GND: 24495.83,13156.65 24425.83,13156.65 24425.83,13089.65 24495.83,13089.65
  region net GND: 24587,12909.65 24517,12909.65 24517,12842.65 24587,12842.65
  region net GND: 24489,12909.65 24419,12909.65 24419,12842.65 24489,12842.65
  region net GND: 24831,12759 24761,12759 24761,12692 24831,12692
  region net SYS_VCC_5: 26184.63,16279 26099,16279 26099,16236.73 26184.63,16236.73
  region net SYS_VCC_5: 24754.61,16242 24716,16242 24716,16165 24754.61,16165
  region net NetC18_1: 21730.39,17479.11 21730.39,17383.11 22367.39,17383.11 22367.39,17479.11
  region net NetC18_1: 21720.39,17479.11 21720.39,17267.11 21777.39,17267.11 21777.39,17479.11
  region net GND: 21505.39,17244.59 21505.39,17149.11 21925.39,17149.11 21925.39,17244.59
  region net GND: 21831.02,17274.11 21831.02,16483.11 22053.39,16483.11 22053.39,17274.11
  region net GND: 21710.55,16991.11 21710.55,16666.11 21857.39,16666.11 21857.39,16991.11
  region net SYS_VCC_5: 22169.39,17290.11 22169.39,16830.11 22370.39,16830.11 22370.39,17290.11
  region net SYS_VCC_5: 22324.39,16844.42 22324.39,16383.11 22370.39,16383.11 22370.39,16844.42
  region net GND: 21831.02,16779.08 21831.02,16386.11 22301.39,16386.11 22301.39,16779.08
  region net SYS_VCC_5: 23034,15742 22926,15742 22926,15704.96 23034,15704.96
  region net VCC12V_SYS: 19800.22,13638.01 19273,13638.01 19273,13544.12 19800.22,13544.12
  region net VCC12V_SYS: 20176.03,13965 20077,13965 20077,13908 20176.03,13908
  region net VCC12V_SYS: 19927,13966 19826,13966 19826,13907 19927,13907
  region net SYS_VCC_5: 21867.13,13554.13 21831,13554.13 21831,13465 21867.13,13465
  region net GND: 21325,16144.01 21254.3,16144.01 21254.3,16109 21325,16109
  region net GND: 20838.99,16499 20838.99,16428.3 20874,16428.3 20874,16499
  rectangle net GND: 21563,15831.99 21633.7,15867
  rectangle net GND: 21741,15586.99 21811.7,15622
  rectangle net GND: 21017,15301.99 21087.7,15337
  rectangle net GND: 20972,15093.99 21042.7,15129
  rectangle net GND: 21552,14897.99 21622.7,14933
  region net GND: 21249.5,14811.39 21178.8,14811.39 21178.8,14776.38 21249.5,14776.38
  region net GND: 21594,14563.29 21523.3,14563.29 21523.3,14528.28 21594,14528.28
  region net GND: 21528,14337.01 21457.3,14337.01 21457.3,14302 21528,14302
  region net GND: 20386.99,14383 20386.99,14312.3 20422,14312.3 20422,14383
  region net GND: 20783,14112.51 20832.99,14162.5 20808.23,14187.26 20758.24,14137.27
  region net GND: 21828.99,13971 21828.99,13900.3 21864,13900.3 21864,13971
  rectangle net GND: 20583,13664.99 20653.7,13700
  rectangle net GND: 20638,13172.99 20708.7,13208
  region net GND: 19780.14,13218 19780.14,13288.7 19745.13,13288.7 19745.13,13218
  region net GND: 21747.01,13514 21747.01,13584.7 21712,13584.7 21712,13514
  region net GND: 22523,13382.01 22452.3,13382.01 22452.3,13347 22523,13347
  region net GND: 22520,13769.04 22453,13769.04 22453,13734.02 22520,13734.02
  region net GND: 22522,14163.01 22451.3,14163.01 22451.3,14128 22522,14128
  region net GND: 22532,14403.01 22461.3,14403.01 22461.3,14368 22532,14368
  region net GND: 23220.99,13797 23220.99,13726.3 23256,13726.3 23256,13797
  region net GND: 23036.47,13797.82 23036.47,13727.12 23071.48,13727.12 23071.48,13797.82
  region net GND: 22829.57,13795.78 22829.57,13725.08 22864.58,13725.08 22864.58,13795.78
  rectangle net GND: 23300,14912.63 23370.7,14947.64
  rectangle net GND: 23296,15112.99 23366.7,15148
  region net GND: 23526.01,14773 23526.01,14843.7 23491,14843.7 23491,14773
  region net GND: 23361,14503.01 23290.3,14503.01 23290.3,14468 23361,14468
  region net GND: 23592,15248.01 23521.3,15248.01 23521.3,15213 23592,15213
  region net GND: 23917.58,14041.01 23846.88,14041.01 23846.88,14006 23917.58,14006
  region net GND: 23778.58,13874.43 23707.88,13874.43 23707.88,13839.42 23778.58,13839.42
  region net GND: 24828,12679.42 24757.3,12679.42 24757.3,12644.41 24828,12644.41
  rectangle net GND: 24446,12514 24510.3,12544.97
  region net GND: 24051.99,12704 24051.99,12633.3 24087,12633.3 24087,12704
  region net GND: 23626.05,12711 23626.05,12640.3 23661.06,12640.3 23661.06,12711
  region net GND: 23210.35,12641.3 23210.35,12570.61 23245.36,12570.61 23245.36,12641.3
  rectangle net GND: 22904,12109.99 22974.7,12145
  rectangle net GND: 23737.34,16190.74 23808.04,16225.75
  rectangle net GND: 24209,15594.99 24279.7,15630
  region net GND: 22519,13711.01 22456,13711.01 22456,13676 22519,13676
  region net GND: 24946.59,14159.43 24946.59,14222.43 24911.57,14222.43 24911.57,14159.43
  region net GND: 22526,13270 22458,13270 22458,13204 22526,13204
  region net GND: 22224.9,16627.56 22156.9,16627.56 22156.9,16561.56 22224.9,16561.56
  region net GND: 22223.61,16712.56 22155.61,16712.56 22155.61,16646.56 22223.61,16646.56
  region net GND: 22222.72,16776.44 22154.72,16776.44 22154.72,16710.44 22222.72,16710.44
  region net GND: 22127.72,16713.78 22059.72,16713.78 22059.72,16647.78 22127.72,16647.78
  region net GND: 22127.72,16776.56 22059.72,16776.56 22059.72,16710.56 22127.72,16710.56
  region net GND: 21857.72,16996.61 21789.72,16996.61 21789.72,16930.61 21857.72,16930.61
  region net GND: 21857.72,16908.56 21789.72,16908.56 21789.72,16842.56 21857.72,16842.56
  region net GND: 21954.72,16890.56 21886.72,16890.56 21886.72,16824.56 21954.72,16824.56
  region net GND: 22041.72,16891.78 21973.72,16891.78 21973.72,16825.78 22041.72,16825.78
  region net GND: 22040.72,16790.87 21972.72,16790.87 21972.72,16724.87 22040.72,16724.87
  region net GND: 21951.72,16792.56 21883.72,16792.56 21883.72,16726.56 21951.72,16726.56
  region net GND: 22040.72,16714.99 21972.72,16714.99 21972.72,16648.99 22040.72,16648.99
  region net GND: 21951.72,16714.56 21883.72,16714.56 21883.72,16648.56 21951.72,16648.56
  region net GND: 22002.72,17110.56 21934.72,17110.56 21934.72,17044.56 22002.72,17044.56
  region net GND: 21448.17,16828.98 21377.48,16828.98 21377.48,16793.97 21448.17,16793.97
  region net GND: 21309.95,17169.84 21239.26,17169.84 21239.26,17134.83 21309.95,17134.83
  region net GND: 21373.17,17526.84 21302.48,17526.84 21302.48,17491.83 21373.17,17491.83
  region net GND: 20192.17,17604.84 20121.48,17604.84 20121.48,17569.83 20192.17,17569.83
  region net GND: 19799.17,17607.84 19728.48,17607.84 19728.48,17572.83 19799.17,17572.83
  region net GND: 20360.85,16326 20360.85,16396.7 20325.83,16396.7 20325.83,16326
  rectangle net GND: 22954.97,17073.27 23025.66,17108.28
  rectangle net GND: 23564.83,16491.83 23635.52,16526.84
  region net GND: 24069.17,14949.48 23998.48,14949.48 23998.48,14914.47 24069.17,14914.47
  rectangle net GND: 24275.39,14605.35 24346.08,14640.36
  region net GND: 23453.17,15761.84 23382.48,15761.84 23382.48,15726.83 23453.17,15726.83
  region net GND: 23554,15561.41 23483.31,15561.41 23483.31,15526.4 23554,15526.4
  region net GND: 23344,15655.48 23273.3,15655.48 23273.3,15620.47 23344,15620.47
  region net SYS_VCC_5: 24551.02,17521 24551.02,17479.89 24626.94,17479.89 24626.94,17521
  rectangle net GND: 21310,15422.46 21380.7,15457.47
  region net VCC5V_SYS: 24560.19,14900.55 24462,14900.55 24462,14860.84 24560.19,14860.84
  region net VCC5V_SYS: 24503,14970.75 24462,14970.75 24462,14860.84 24503,14860.84
  region net VCC12V_SYS: 21691,16990.09 21654.53,16990.09 21654.53,16605 21691,16605
  region net VCC12V_SYS: 21690.97,16935 21495,16935 21495,16521.54 21690.97,16521.54
  region net VCC12V_SYS: 21756,16619 21496,16619 21496,16521 21756,16521
  region net GND: 21109.99,16450 21109.99,16379.3 21145,16379.3 21145,16450
  region net GND: 21168,14280.01 21097.3,14280.01 21097.3,14245 21168,14245
  region net GND: 23971.14,17515.79 23900.44,17515.79 23900.44,17480.78 23971.14,17480.78
  region net GND: 23972,17454.01 23901.3,17454.01 23901.3,17419 23972,17419
  region net VCC12V_SYS: 20983,16749 20965,16731 20701.3,16731 20685.3,16747 20685.3,17188.09 20699.75,17202.55 20963.45,17202.55 20983,17183
  region net GND: 25645.5,16369.23 25663,16351.73 25663,15976 25651,15964 25438.83,15964 25423,15979.83 25423,16357.48 25434.75,16369.23
  region net GND: 28211.5,14795.23 28229,14777.73 28229,14402 28217,14390 28004.83,14390 27989,14405.83 27989,14783.48 28000.75,14795.23
  region net GND: 24406.83,13195 24603.58,13195 24610.58,13188 24610.58,12796.57 24593,12779 24422.46,12779 24402.99,12798.47 24402.99,13191.16
  region net NetQ10_2: 24440.71,13626.58 24445.58,13621.71 24445.58,13557.33 24434.76,13546.5 23912.18,13546.5 23890.53,13524.85 23766.43,13524.85 23761.58,13529.71 23761.58,13626.58
  region net NetC53_1: 23945.06,13459.89 24430.43,13459.89 24443.21,13447.11 24443.21,13258.12 24418.6,13233.51 24315.25,13233.51 24250.39,13168.65 24250.39,12905.09 24224.48,12879.18 23842.81,12879.18 23781.32,12940.68 23781.32,13312.63 23928.58,13459.89 23940.06,13459.89
  region net SYS_VCC_5: 24615,15091 24548,15091 24548,15016 24615,15016
  region net POWER: 20615,16741.59 20600.41,16727 20291,16727 20275,16743 20275,17184.09 20289.45,17198.55 20602.45,17198.55 20615,17186
  region net SYS_VCC_5: 22917,16490 22792,16490 22792,16385 22917,16385
  pour cut-out: 21481,17650 21481,16360.64 21531.98,16360.64 22442,16360.64 22442,17648 22442,17650
  region net NetQ12_2: 23548.41,13630.17 23581.73,13596.85 23581.73,13060.02 23558.58,13036.87 23441.11,13036.87 23421.63,13056.35 23421.63,13610.87 23440.92,13630.17
  pour cut-out: 21887,13721.46 21886.54,13721 21817,13721 21817,13657.35 21887,13657.35
  pour cut-out: 23116,17065 23115.61,17064.61 22920,17064.61 22920,16875 22919.56,16874.56 23116,16874.56
  pour cut-out: 24427,15095.6 24387,15095.6 24387,14996.85 24427,14996.85
  pour cut-out: 20345,13644 20345,13726.3 20395,13726.3 20395,13644
  region net GND: 25782.91,16435.45 ccw(c25860.1,16435.45) 25860.1,16358.26 ccw(c25860.1,16435.45) 25937.29,16435.45 ccw(c25860.1,16435.45) 25860.1,16512.64 ccw(c25860.1,16435.45)
  region net GND: 27607.28,13793.71 ccw(c27789.57,13793.71) 27789.57,13611.42 ccw(c27789.57,13793.71) 27971.86,13793.71 ccw(c27789.57,13793.71) 27789.57,13976.01 ccw(c27789.57,13793.71)
  region net GND: 27717.26,16360.64 ccw(c27899.55,16360.64) 27899.55,16178.35 ccw(c27899.55,16360.64) 28081.85,16360.64 ccw(c27899.55,16360.64) 27899.55,16542.93 ccw(c27899.55,16360.64)
  region net GND: 25571.6,13864.58 ccw(c25753.89,13864.58) 25753.89,13682.29 ccw(c25753.89,13864.58) 25936.18,13864.58 ccw(c25753.89,13864.58) 25753.89,14046.87 ccw(c25753.89,13864.58)
  region net GND: 24872.71,12525 ccw(c25055,12525) 25055,12342.71 ccw(c25055,12525) 25237.29,12525 ccw(c25055,12525) 25055,12707.29 ccw(c25055,12525)
  region net GND: 22207.71,15900 ccw(c22390,15900) 22390,15717.71 ccw(c22390,15900) 22572.29,15900 ccw(c22390,15900) 22390,16082.29 ccw(c22390,15900)
  region net GND: 19441.71,16197 ccw(c19624,16197) 19624,16014.71 ccw(c19624,16197) 19806.29,16197 ccw(c19624,16197) 19624,16379.29 ccw(c19624,16197)

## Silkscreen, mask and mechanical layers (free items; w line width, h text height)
Top Overlay:
  lines w7: 16136,12091.54 31929,12091.54 ; 16452,17643.46 31426,17643.46 ; 19246.54,11175 19246.54,18537 ; 25047.17,11214 25047.17,18722
  text "C281-ICU-DS-B-V111" at 22700,17550 h32
Bottom Overlay:
  lines w7: 18155,12091.54 29517,12091.54 ; 18580,18962 18591,18973 ; 18591,17643.46 28852,17643.46 ; 19246.54,10290 19246.54,18105 ; 25047.17,10457 25047.17,18537
  lines w10: 25027.48,11875 ccw(c25027.59,12111.11) 25263.7,12111 25263.7,17625.78 ccw(c25029.48,17625.78) 25029.48,17860
  text "C281-ICU-DS-B-V111" at 24922,17559 h32
  text "PWR" at 19225,16554 h32 r270
  text "GND" at 19309,16097 h32 r90
Drill Drawing:
  text ".legend" at 28532,11945 h60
